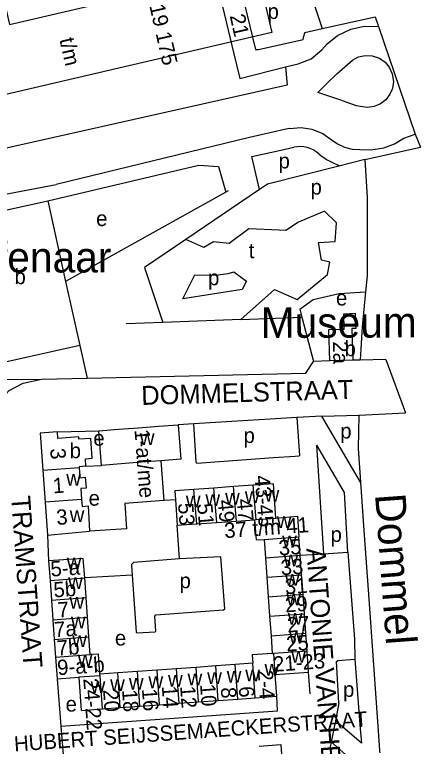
# Model space of a CAD drawing. Extents: x 160673 to 161924, y 382258 to 384145.
# Drawn here: x 161677.7 to 161784.3, y 383511.4 to 383703.4 of the extents above; entities that cross this region are included whole.
import ezdxf

# ---------------------------------------------------------------- set-up
doc = ezdxf.new("R2010")
doc.units = 0
for name, color, linetype in [('BLT_Basislijn', 7, 'Continuous'), ('BLT_Bebouwing', 7, 'Continuous'), ('BLT_Bebouwing_beschrifting', 7, 'Continuous'), ('BLT_Centroide', 7, 'Continuous'), ('BLT_Huisnummer', 7, 'Continuous'), ('BLT_Huisnummer_ tussenligend', 7, 'Continuous'), ('BLT_Huisnummer_reeks', 7, 'Continuous'), ('BLT_Huisnummer_zonder_bebouwing', 7, 'Continuous'), ('BLT_Onderverdeling_panden', 7, 'Continuous'), ('BLT_Plantopo', 7, 'Continuous'), ('BLT_Straatnaam', 7, 'Continuous'), ('BLT_Straatnaam_verkleind', 7, 'Continuous'), ('BLT_Vlakafsluiter', 7, 'Continuous'), ('BLT_Waternaam_spoorwegen', 7, 'Continuous')]:
    doc.layers.add(name, color=color, linetype=linetype)

msp = doc.modelspace()

# ---------------------------------------------------------------- linework, layer by layer
at = {"layer": 'BLT_Basislijn'}
for p, q in [((161752.78, 383716.87), (161758.51, 383699.76)), ((161758.51, 383699.76), (161772.4, 383702.86)), ((161735.29, 383693.17), (161736.85, 383686.65)), ((161736.85, 383686.65), (161748.83, 383689.69)), ((161749.94, 383673.47), (161748.6, 383673.21)), ((161739.4, 383671.12), (161688.55, 383658.79)), ((161769.69, 383665.34), (161784.3, 383668.61)), ((161769.69, 383665.34), (161763.26, 383663.72)), ((161763.26, 383663.72), (161744.08, 383658.88)), ((161744.08, 383658.88), (161741.98, 383657.45)), ((161733.2, 383656.76), (161691.07, 383633.34)), ((161741.98, 383657.45), (161722.68, 383644.37)), ((161733.83, 383657.11), (161733.2, 383656.76)), ((161716.61, 383622.57), (161707.01, 383622.2)), ((161737.08, 383623.35), (161716.61, 383622.57)), ((161694.81, 383616.45), (161696.71, 383607.88)), ((161760.52, 383612.42), (161756.19, 383612.24)), ((161768.47, 383612.59), (161766.54, 383612.63)), ((161775.24, 383612.8), (161768.47, 383612.59)), ((161657.88, 383607.4), (161684.77, 383607.61)), ((161768.16, 383598.15), (161780.4, 383598.77)), ((161739.02, 383596.8), (161724.74, 383595.92)), ((161744.81, 383597.16), (161739.02, 383596.8)), ((161751.82, 383597.59), (161744.81, 383597.16)), ((161758.42, 383597.93), (161751.82, 383597.59)), ((161758.42, 383597.93), (161768.16, 383598.15)), ((161768.58, 383580.6), (161758.42, 383597.93)), ((161768.16, 383598.15), (161767.96, 383589.44)), ((161724.74, 383595.92), (161720.65, 383595.67)), ((161688.95, 383593.78), (161699.8, 383594.07)), ((161764.4, 383577.83), (161757.08, 383590.33)), ((161758.89, 383561.78), (161757.08, 383590.33)), ((161767.96, 383589.44), (161768.58, 383580.6)), ((161716.13, 383586.18), (161716.92, 383575.72)), ((161696.43, 383584.77), (161700.49, 383584.99)), ((161768.58, 383580.6), (161769.48, 383567.91)), ((161765.24, 383562.18), (161764.4, 383577.83)), ((161719.92, 383575.95), (161716.92, 383575.72)), ((161721.02, 383560.41), (161720.4, 383569.25)), ((161686.33, 383566.61), (161686.61, 383559.91)), ((161758.89, 383561.78), (161765.24, 383562.18)), ((161752.72, 383561.36), (161758.89, 383561.78)), ((161708.54, 383556.17), (161696.1, 383555.4)), ((161755.32, 383524.98), (161754.93, 383530.64)), ((161688.84, 383528.91), (161689.86, 383516.45)), ((161762.89, 383522.57), (161762.02, 383517.89)), ((161689.86, 383516.45), (161691.33, 383498.55)), ((161760.94, 383512.21), (161761.87, 383517.06)), ((161762.02, 383517.89), (161761.87, 383517.06)), ((161768.8, 383511.99), (161762.02, 383517.89))]:
    msp.add_line(p, q, dxfattribs=at)
for points in [[(161729.62, 383741.51), (161730.04, 383739.48), (161740.96, 383694.23), (161741.8, 383694.23), (161753.53, 383696.92), (161753.91, 383698.73), (161758.51, 383699.76)], [(161730.58, 383713.19), (161732.24, 383705.89), (161735.29, 383693.17)], [(161748.83, 383689.69), (161752.16, 383690.49), (161755.6, 383691.8), (161758.41, 383694.19), (161759.8, 383695.79), (161762.51, 383697.97), (161766.01, 383699.64), (161769.53, 383700.4), (161773.28, 383700.32)], [(161748.83, 383689.69), (161749.31, 383684.86), (161650.8, 383662.81), (161647.76, 383667.52), (161637.6, 383664.67), (161636.93, 383659.78), (161564.43, 383643.62), (161563.17, 383648.74)], [(161749.94, 383673.47), (161752.98, 383673.75), (161755.75, 383673.35), (161758.67, 383672.19), (161760.89, 383670.64), (161762.54, 383669.47), (161764.39, 383668.61), (161766.35, 383668.11), (161768.38, 383667.98), (161771.29, 383667.91), (161774.68, 383668.47), (161777.48, 383669.49), (161779.99, 383670.94), (161782.9, 383672.04)], [(161748.6, 383673.21), (161739.4, 383671.12)], [(161741.98, 383657.45), (161740.04, 383666.17), (161747.64, 383667.86), (161748.79, 383668.09), (161751.01, 383668.58)], [(161757.6, 383666.88), (161757.61, 383666.86), (161757.63, 383666.85)], [(161769.69, 383665.34), (161770.31, 383655.36), (161770.31, 383644.3), (161770.31, 383634.77), (161769.88, 383630.56)], [(161686.37, 383654.52), (161726.11, 383663.89), (161731.26, 383663.53), (161733.2, 383656.76)], [(161659.47, 383653.24), (161688.55, 383658.79)], [(161751.94, 383628.59), (161759.88, 383635.15), (161760.51, 383638.36), (161758.34, 383638.9), (161757.52, 383643.52), (161761.92, 383643.85), (161762.25, 383648.68), (161759.12, 383651.77), (161752.3, 383648.93), (161748.91, 383646.68), (161747.22, 383646.77)], [(161747.22, 383646.77), (161739.25, 383647.18), (161734.05, 383643.28), (161729.9, 383643.77), (161727.4, 383642.24), (161722.68, 383644.37)], [(161722.68, 383644.37), (161711.8, 383636.98), (161716.61, 383622.57)], [(161721.9, 383628.77), (161725.01, 383635.06), (161730.5, 383634.96), (161733.76, 383635.37), (161735.26, 383635.88), (161738.57, 383633.39), (161737.49, 383631.19), (161721.9, 383628.77)], [(161737.08, 383623.35), (161746, 383631.16), (161751.94, 383628.59)], [(161752.6, 383626.07), (161756.11, 383628.61), (161762.93, 383630.16), (161769.88, 383630.56)], [(161769.88, 383630.56), (161768.97, 383621.42), (161768.47, 383612.59)], [(161752.6, 383626.07), (161753.15, 383623.96)], [(161737.08, 383623.35), (161753.15, 383623.96)], [(161753.15, 383623.96), (161756.19, 383612.24)], [(161696.71, 383607.88), (161754.16, 383609.21), (161756.19, 383612.24)], [(161672.44, 383572.56), (161671, 383592.52), (161671.52, 383596.81), (161672.76, 383599.82), (161674.29, 383602.6), (161676.22, 383604.62), (161679.9, 383606.62), (161684.77, 383607.61)], [(161684.77, 383607.61), (161696.71, 383607.88)], [(161751.82, 383597.59), (161752.56, 383587.59), (161752.4, 383587.43), (161751.43, 383587.36)], [(161745.68, 383586.94), (161725.58, 383585.49), (161725.39, 383585.84), (161724.74, 383595.92)], [(161751.43, 383587.36), (161745.68, 383586.94)], [(161716.92, 383575.72), (161706.67, 383574.94), (161707.06, 383568.29), (161697.39, 383567.73)], [(161769.48, 383567.91), (161770.84, 383548.66), (161773.73, 383507.7)], [(161765.24, 383562.18), (161766.96, 383539.33), (161767.11, 383534.1)], [(161721.02, 383560.41), (161708.91, 383559.5), (161708.42, 383558.96), (161708.46, 383557.29), (161708.54, 383556.17)], [(161708.54, 383556.17), (161709.65, 383541.16), (161709.81, 383540.99), (161714.59, 383541.25), (161714.75, 383541.41), (161714.52, 383545.33), (161714.75, 383545.68), (161732.53, 383547.04), (161732.88, 383547.27), (161731.86, 383560.95), (161721.02, 383560.41)], [(161762.89, 383522.57), (161762.23, 383533.44), (161762.62, 383533.72), (161767.11, 383534.1)], [(161767.11, 383534.1), (161768.51, 383515.8), (161768.8, 383511.99)], [(161746.76, 383520.52), (161746.59, 383524.3)], [(161689.86, 383516.45), (161746.76, 383520.52)], [(161767.42, 383475.92), (161765.69, 383499.42), (161765.46, 383499.68), (161761.6, 383499.66), (161761.44, 383500.07), (161760.72, 383511.06), (161760.94, 383512.21)], [(161769.9, 383496.48), (161769.19, 383505.02), (161760.94, 383512.21)]]:
    msp.add_lwpolyline(points, dxfattribs=at)
msp.add_lwpolyline([(161757.39, 383682.95), (161759.76, 383685.4), (161762.38, 383687.84), (161765.18, 383690.36), (161766.43, 383691.49), (161768.02, 383692.32), (161769.82, 383692.71), (161771.67, 383692.61), (161773.55, 383691.95), (161775.01, 383690.91), (161776.11, 383689.62), (161776.92, 383687.89), (161777.21, 383685.89), (161776.97, 383684.06), (161776.31, 383682.49), (161775.18, 383681.02), (161773.83, 383679.98), (161772.18, 383679.28), (161770.34, 383679.04), (161768.57, 383679.28), (161767.55, 383679.45), (161764.78, 383680.47), (161763.36, 383680.99)], close=True, dxfattribs=at)
for centre, radius, start, end in [((161752.61, 383661.17), 7.58, 48.8197, 102.1616), ((161768.1, 383679.04), 16.07, 229.3679, 252.477)]:
    msp.add_arc(centre, radius, start, end, dxfattribs=at)
at = {"layer": 'BLT_Bebouwing'}
for p, q in [((161691.07, 383633.34), (161694.81, 383616.45)), ((161766.54, 383612.63), (161760.52, 383612.42)), ((161705.01, 383594.47), (161710.23, 383594.87)), ((161710.23, 383594.87), (161715.44, 383595.27)), ((161715.44, 383595.27), (161720.65, 383595.67)), ((161699.8, 383594.07), (161705.01, 383594.47)), ((161700.49, 383584.99), (161699.8, 383594.07)), ((161705.71, 383585.39), (161700.49, 383584.99)), ((161710.92, 383585.79), (161705.71, 383585.39)), ((161716.13, 383586.18), (161710.92, 383585.79)), ((161740.37, 383579.79), (161735.18, 383579.41)), ((161730, 383579.04), (161724.81, 383578.67)), ((161735.18, 383579.41), (161730, 383579.04)), ((161719.92, 383575.95), (161720.4, 383569.25)), ((161725.59, 383569.62), (161730.78, 383570)), ((161730.78, 383570), (161735.97, 383570.37)), ((161735.97, 383570.37), (161740.75, 383570.71)), ((161752.72, 383561.36), (161752.38, 383566.21)), ((161743.24, 383565.55), (161743.59, 383560.71)), ((161743.59, 383560.71), (161743.96, 383555.59)), ((161753.09, 383556.24), (161752.72, 383561.36)), ((161686.61, 383559.91), (161686.98, 383554.74)), ((161686.98, 383554.74), (161687.35, 383549.58)), ((161743.96, 383555.59), (161744.33, 383550.47)), ((161753.46, 383551.12), (161753.09, 383556.24)), ((161753.83, 383546), (161753.46, 383551.12)), ((161687.35, 383549.58), (161687.72, 383544.41)), ((161696.84, 383545.07), (161696.47, 383550.23)), ((161744.33, 383550.47), (161744.69, 383545.35)), ((161697.21, 383539.9), (161696.84, 383545.07)), ((161744.69, 383545.35), (161745.06, 383540.23)), ((161754.19, 383540.88), (161753.83, 383546)), ((161687.72, 383544.41), (161688.09, 383539.25)), ((161688.09, 383539.25), (161688.43, 383534.6)), ((161697.54, 383535.25), (161697.21, 383539.9)), ((161745.06, 383540.23), (161745.39, 383535.58)), ((161754.53, 383536.24), (161754.19, 383540.88)), ((161754.93, 383530.64), (161754.53, 383536.24)), ((161688.43, 383534.6), (161688.84, 383528.91)), ((161720.23, 383531.53), (161715.09, 383531.16)), ((161725.38, 383531.9), (161720.23, 383531.53)), ((161730.52, 383532.27), (161725.38, 383531.9)), ((161735.66, 383532.64), (161730.52, 383532.27)), ((161740.24, 383532.97), (161735.66, 383532.64)), ((161704.8, 383530.43), (161700.08, 383530.09)), ((161709.95, 383530.79), (161704.8, 383530.43)), ((161715.09, 383531.16), (161709.95, 383530.79)), ((161746.18, 383530.02), (161754.93, 383530.64)), ((161746.59, 383524.3), (161746.18, 383530.02)), ((161688.84, 383528.91), (161694.54, 383529.32)), ((161736.31, 383523.56), (161740.89, 383523.89)), ((161740.89, 383523.89), (161746.59, 383524.3)), ((161710.6, 383521.72), (161715.74, 383522.09)), ((161715.74, 383522.09), (161720.88, 383522.46)), ((161720.88, 383522.46), (161726.02, 383522.83)), ((161726.02, 383522.83), (161731.17, 383523.2)), ((161731.17, 383523.2), (161736.31, 383523.56)), ((161700.73, 383521.01), (161705.45, 383521.35)), ((161705.45, 383521.35), (161710.6, 383521.72))]:
    msp.add_line(p, q, dxfattribs=at)
for points in [[(161660.46, 383648.78), (161686.37, 383654.52), (161691.07, 383633.34)], [(161760.52, 383612.42), (161760.28, 383620.68), (161764.3, 383620.8), (161764.18, 383624.85), (161767.18, 383624.96), (161767.3, 383620.96), (161766.3, 383620.92)], [(161766.3, 383620.92), (161766.54, 383612.63)], [(161694.81, 383616.45), (161668.9, 383610.7)], [(161720.65, 383595.67), (161721.35, 383586.58), (161716.13, 383586.18)], [(161688.95, 383593.78), (161684.4, 383593.48)], [(161684.4, 383593.48), (161685.1, 383583.7)], [(161696.43, 383584.77), (161696.29, 383586.71), (161698.07, 383586.84), (161697.69, 383592.08), (161694.56, 383591.85), (161694.51, 383592.48), (161689.07, 383592.09), (161688.95, 383593.78)], [(161685.1, 383583.7), (161685.7, 383575.32)], [(161696.43, 383584.77), (161694.64, 383584.61), (161694.65, 383584.43)], [(161694.65, 383584.43), (161694.85, 383581.75), (161696.25, 383581.85), (161696.46, 383578.98), (161695.06, 383578.87), (161695.26, 383576.01)], [(161746.34, 383571.15), (161745.69, 383580.17), (161740.37, 383579.79)], [(161724.81, 383578.67), (161719.75, 383578.31), (161719.92, 383575.95)], [(161695.26, 383576.01), (161695.4, 383574.22), (161696.96, 383574.33), (161697.39, 383567.73)], [(161685.7, 383575.32), (161686.33, 383566.61)], [(161740.75, 383570.71), (161741.14, 383565.4), (161743.24, 383565.55)], [(161746.34, 383571.15), (161751.99, 383571.6), (161752.38, 383566.21)], [(161720.4, 383569.25), (161725.39, 383569.61), (161725.59, 383569.62)], [(161686.33, 383566.61), (161697.39, 383567.73)], [(161696.1, 383555.4), (161695.73, 383560.56), (161686.61, 383559.91)], [(161696.47, 383550.23), (161696.46, 383550.39), (161696.1, 383555.4)], [(161700.08, 383530.09), (161699.7, 383535.41), (161697.54, 383535.25)], [(161745.39, 383535.58), (161740.08, 383535.2), (161740.24, 383532.97)], [(161694.54, 383529.32), (161695.17, 383520.61), (161700.73, 383521.01)], [(161741.95, 383511.22), (161747.6, 383511.64), (161748.26, 383502.86)]]:
    msp.add_lwpolyline(points, dxfattribs=at)
at = {"layer": 'BLT_Onderverdeling_panden'}
for p, q in [((161685.1, 383583.7), (161694.65, 383584.43)), ((161741.16, 383570.74), (161740.37, 383579.79)), ((161725.59, 383569.62), (161724.81, 383578.67)), ((161730.78, 383570), (161730, 383579.04)), ((161735.97, 383570.37), (161735.18, 383579.41)), ((161695.26, 383576.01), (161685.7, 383575.32)), ((161740.75, 383570.71), (161741.16, 383570.74)), ((161741.16, 383570.74), (161746.34, 383571.15)), ((161743.24, 383565.55), (161752.38, 383566.21)), ((161743.59, 383560.71), (161752.72, 383561.36)), ((161686.98, 383554.74), (161696.1, 383555.4)), ((161743.96, 383555.59), (161753.09, 383556.24)), ((161744.33, 383550.47), (161753.46, 383551.12)), ((161687.35, 383549.58), (161696.47, 383550.23)), ((161687.72, 383544.41), (161696.84, 383545.07)), ((161744.69, 383545.35), (161753.83, 383546)), ((161688.09, 383539.25), (161697.21, 383539.9)), ((161745.06, 383540.23), (161754.19, 383540.88)), ((161745.39, 383535.58), (161745.78, 383535.61)), ((161745.78, 383535.61), (161754.53, 383536.24)), ((161746.18, 383530.02), (161745.78, 383535.61)), ((161688.43, 383534.6), (161697.54, 383535.25)), ((161720.88, 383522.46), (161720.23, 383531.53)), ((161726.02, 383522.83), (161725.38, 383531.9)), ((161731.17, 383523.2), (161730.52, 383532.27)), ((161736.31, 383523.56), (161735.66, 383532.64)), ((161740.89, 383523.89), (161740.24, 383532.97)), ((161700.11, 383529.72), (161694.54, 383529.32)), ((161700.11, 383529.72), (161700.08, 383530.09)), ((161700.73, 383521.01), (161700.11, 383529.72)), ((161705.45, 383521.35), (161704.8, 383530.43)), ((161710.6, 383521.72), (161709.95, 383530.79)), ((161715.74, 383522.09), (161715.09, 383531.16))]:
    msp.add_line(p, q, dxfattribs=at)
at = {"layer": 'BLT_Plantopo'}
for p, q in [((161772.4, 383702.86), (161773.28, 383700.32)), ((161773.28, 383700.32), (161782.9, 383672.04)), ((161782.9, 383672.04), (161784.3, 383668.61))]:
    msp.add_line(p, q, dxfattribs=at)
msp.add_lwpolyline([(161630.73, 383729.23), (161719.7, 383749.96), (161724.89, 383727.66), (161672.91, 383715.55), (161676.33, 383700.87), (161741.21, 383715.99), (161745.23, 383698.73), (161642.62, 383674.82), (161638.62, 383692), (161642.66, 383692.94), (161639.18, 383707.83), (161635.89, 383707.06)], close=True, dxfattribs=at)
at = {"layer": 'BLT_Vlakafsluiter'}
msp.add_line((161775.24, 383612.8), (161780.4, 383598.77), dxfattribs=at)

# ---------------------------------------------------------------- texts
at = {"layer": 'BLT_Bebouwing_beschrifting'}
msp.add_text('De Effenaar', height=8, dxfattribs=at).set_placement((161646.02, 383635.68))
msp.add_text('Museum', height=8, rotation=0.1745, dxfattribs=at).set_placement((161742.34, 383618.48))
at = {"layer": 'BLT_Centroide'}
for s, p in [('p', (161744.14, 383702.3)), ('p', (161747.03, 383663.02)), ('p', (161755.43, 383656.14)), ('e', (161699.1, 383647.87)), ('t', (161739.19, 383639.42)), ('b', (161677.64, 383632.61)), ('p', (161728.5, 383632.33)), ('e', (161762.12, 383627)), ('b', (161764.37, 383613.68)), ('p', (161763.24, 383592.04)), ('e', (161698.36, 383590.17)), ('w', (161710.57, 383590.31)), ('p', (161737.83, 383590.87)), ('b', (161692.14, 383586.87)), ('w', (161691.23, 383579.67)), ('w', (161732.98, 383574.7)), ('w', (161738.17, 383575.08)), ('w', (161743.36, 383575.45)), ('e', (161697.11, 383574.39)), ('w', (161722.67, 383573.97)), ('w', (161727.8, 383574.33)), ('w', (161692.14, 383570.11)), ('w', (161746.56, 383568.5)), ('p', (161760.69, 383564.87)), ('w', (161747.98, 383563.47)), ('w', (161691.36, 383557.66)), ('w', (161748.34, 383558.47)), ('w', (161748.71, 383553.34)), ('w', (161691.73, 383552.5)), ('p', (161721.01, 383552.7)), ('w', (161749.08, 383548.25)), ('w', (161692.09, 383547.31)), ('w', (161692.47, 383542.16)), ('w', (161749.45, 383543.12)), ('w', (161749.8, 383538.22)), ('w', (161692.82, 383537.25)), ('e', (161704.03, 383537.65)), ('w', (161750.35, 383533.12)), ('w', (161694.27, 383532.16)), ('w', (161743.33, 383529.75)), ('w', (161717.98, 383526.81)), ('w', (161723.12, 383527.19)), ('w', (161728.27, 383527.55)), ('w', (161733.42, 383527.91)), ('w', (161738.28, 383528.27)), ('w', (161697.64, 383525.16)), ('w', (161702.77, 383525.72)), ('w', (161707.7, 383526.06)), ('w', (161712.84, 383526.44)), ('p', (161763.97, 383524.15)), ('e', (161691.08, 383520.29))]:
    msp.add_text(s, height=4, dxfattribs=at).set_placement(p)
at = {"layer": 'BLT_Huisnummer'}
for s, rotation, p in [('2a', 271.6847, (161761.28, 383617.55)), ('49', 274.9636, (161731.05, 383575.8)), ('53', 274.1059, (161720.61, 383574.99)), ('35', 4.1026, (161747.2, 383561.3)), ('33', 4.1021, (161747.72, 383556.1)), ('5b', 4.1035, (161688.03, 383550.28)), ('29', 4.1021, (161748.86, 383546.35)), ('7', 4.1039, (161689.11, 383545)), ('7a', 4.1039, (161688.18, 383539.82)), ('7b', 4.0986, (161688.89, 383534.95)), ('25', 4.1017, (161749.15, 383536.07)), ('16', 274.1045, (161711.12, 383526.22)), ('14', 274.1045, (161716.35, 383526.97)), ('10', 274.0986, (161726.39, 383527.45)), ('6', 274.0986, (161736.56, 383526.83))]:
    msp.add_text(s, height=4, rotation=rotation, dxfattribs=at).set_placement(p)
at = {"layer": 'BLT_Huisnummer_ tussenligend'}
for s, rotation, p in [('47', 274.9636, (161736.02, 383576.06)), ('51', 274.9636, (161725.62, 383574.85)), ('31', 4.1021, (161748.81, 383551.11)), ('27', 4.1017, (161749.39, 383541.05)), ('20', 274.1045, (161700.91, 383526.01)), ('18', 274.1045, (161705.9, 383525.97)), ('12', 274.0986, (161721.17, 383526.94)), ('8', 274.0986, (161731.84, 383526.57))]:
    msp.add_text(s, height=4, rotation=rotation, dxfattribs=at).set_placement(p)
at = {"layer": 'BLT_Huisnummer_reeks'}
for s, rotation, p in [('1-at/me', 274.3659, (161709.17, 383594.35)), ('3', 274.0982, (161687.01, 383589.39)), ('1', 4.1037, (161687.84, 383577.62)), ('43-45', 274.9601, (161740.7, 383582.25)), ('3', 4.1037, (161688.76, 383569.32)), ('37 t/m 41', 4.1021, (161732.89, 383565.86)), ('5-a', 4.1026, (161687.24, 383555.75)), ('21-23', 4.094, (161745.73, 383530.73)), ('9-a-b', 4.0992, (161689, 383529.84)), ('2-4', 274.0991, (161741.54, 383531.16)), ('24-22', 274.1053, (161695.72, 383528.92))]:
    msp.add_text(s, height=4, rotation=rotation, dxfattribs=at).set_placement(p)
at = {"layer": 'BLT_Huisnummer_zonder_bebouwing'}
for s, p in [('19 175', (161713.06, 383705.76)), ('21', (161734.16, 383703.14)), ('t/m', (161689.43, 383696.91))]:
    msp.add_text(s, height=4, rotation=282.7763, dxfattribs=at).set_placement(p)
at = {"layer": 'BLT_Straatnaam'}
for s, rotation, p in [('DOMMELSTRAAT', 1.6847, (161711.02, 383600.85)), ('TRAMSTRAAT', 274.1772, (161676.75, 383576.84)), ('ANTONIE VAN HEMERTSTRAAT', 274.147, (161754.33, 383563.14))]:
    msp.add_text(s, height=5, rotation=rotation, dxfattribs=at).set_placement(p)
at = {"layer": 'BLT_Straatnaam_verkleind'}
msp.add_text('HUBERT SEIJSSEMAECKERSTRAAT', height=4, rotation=4.0719, dxfattribs=at).set_placement((161677.66, 383509.79))
at = {"layer": 'BLT_Waternaam_spoorwegen'}
msp.add_text('Dommel', height=8, rotation=274.2296, dxfattribs=at).set_placement((161772.37, 383577.34))

doc.saveas('drawing.dxf')
